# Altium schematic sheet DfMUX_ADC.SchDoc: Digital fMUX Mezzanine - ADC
size 513 x 386 mm; Engineer: M.Dobbs, McGill U.; Revision: 4
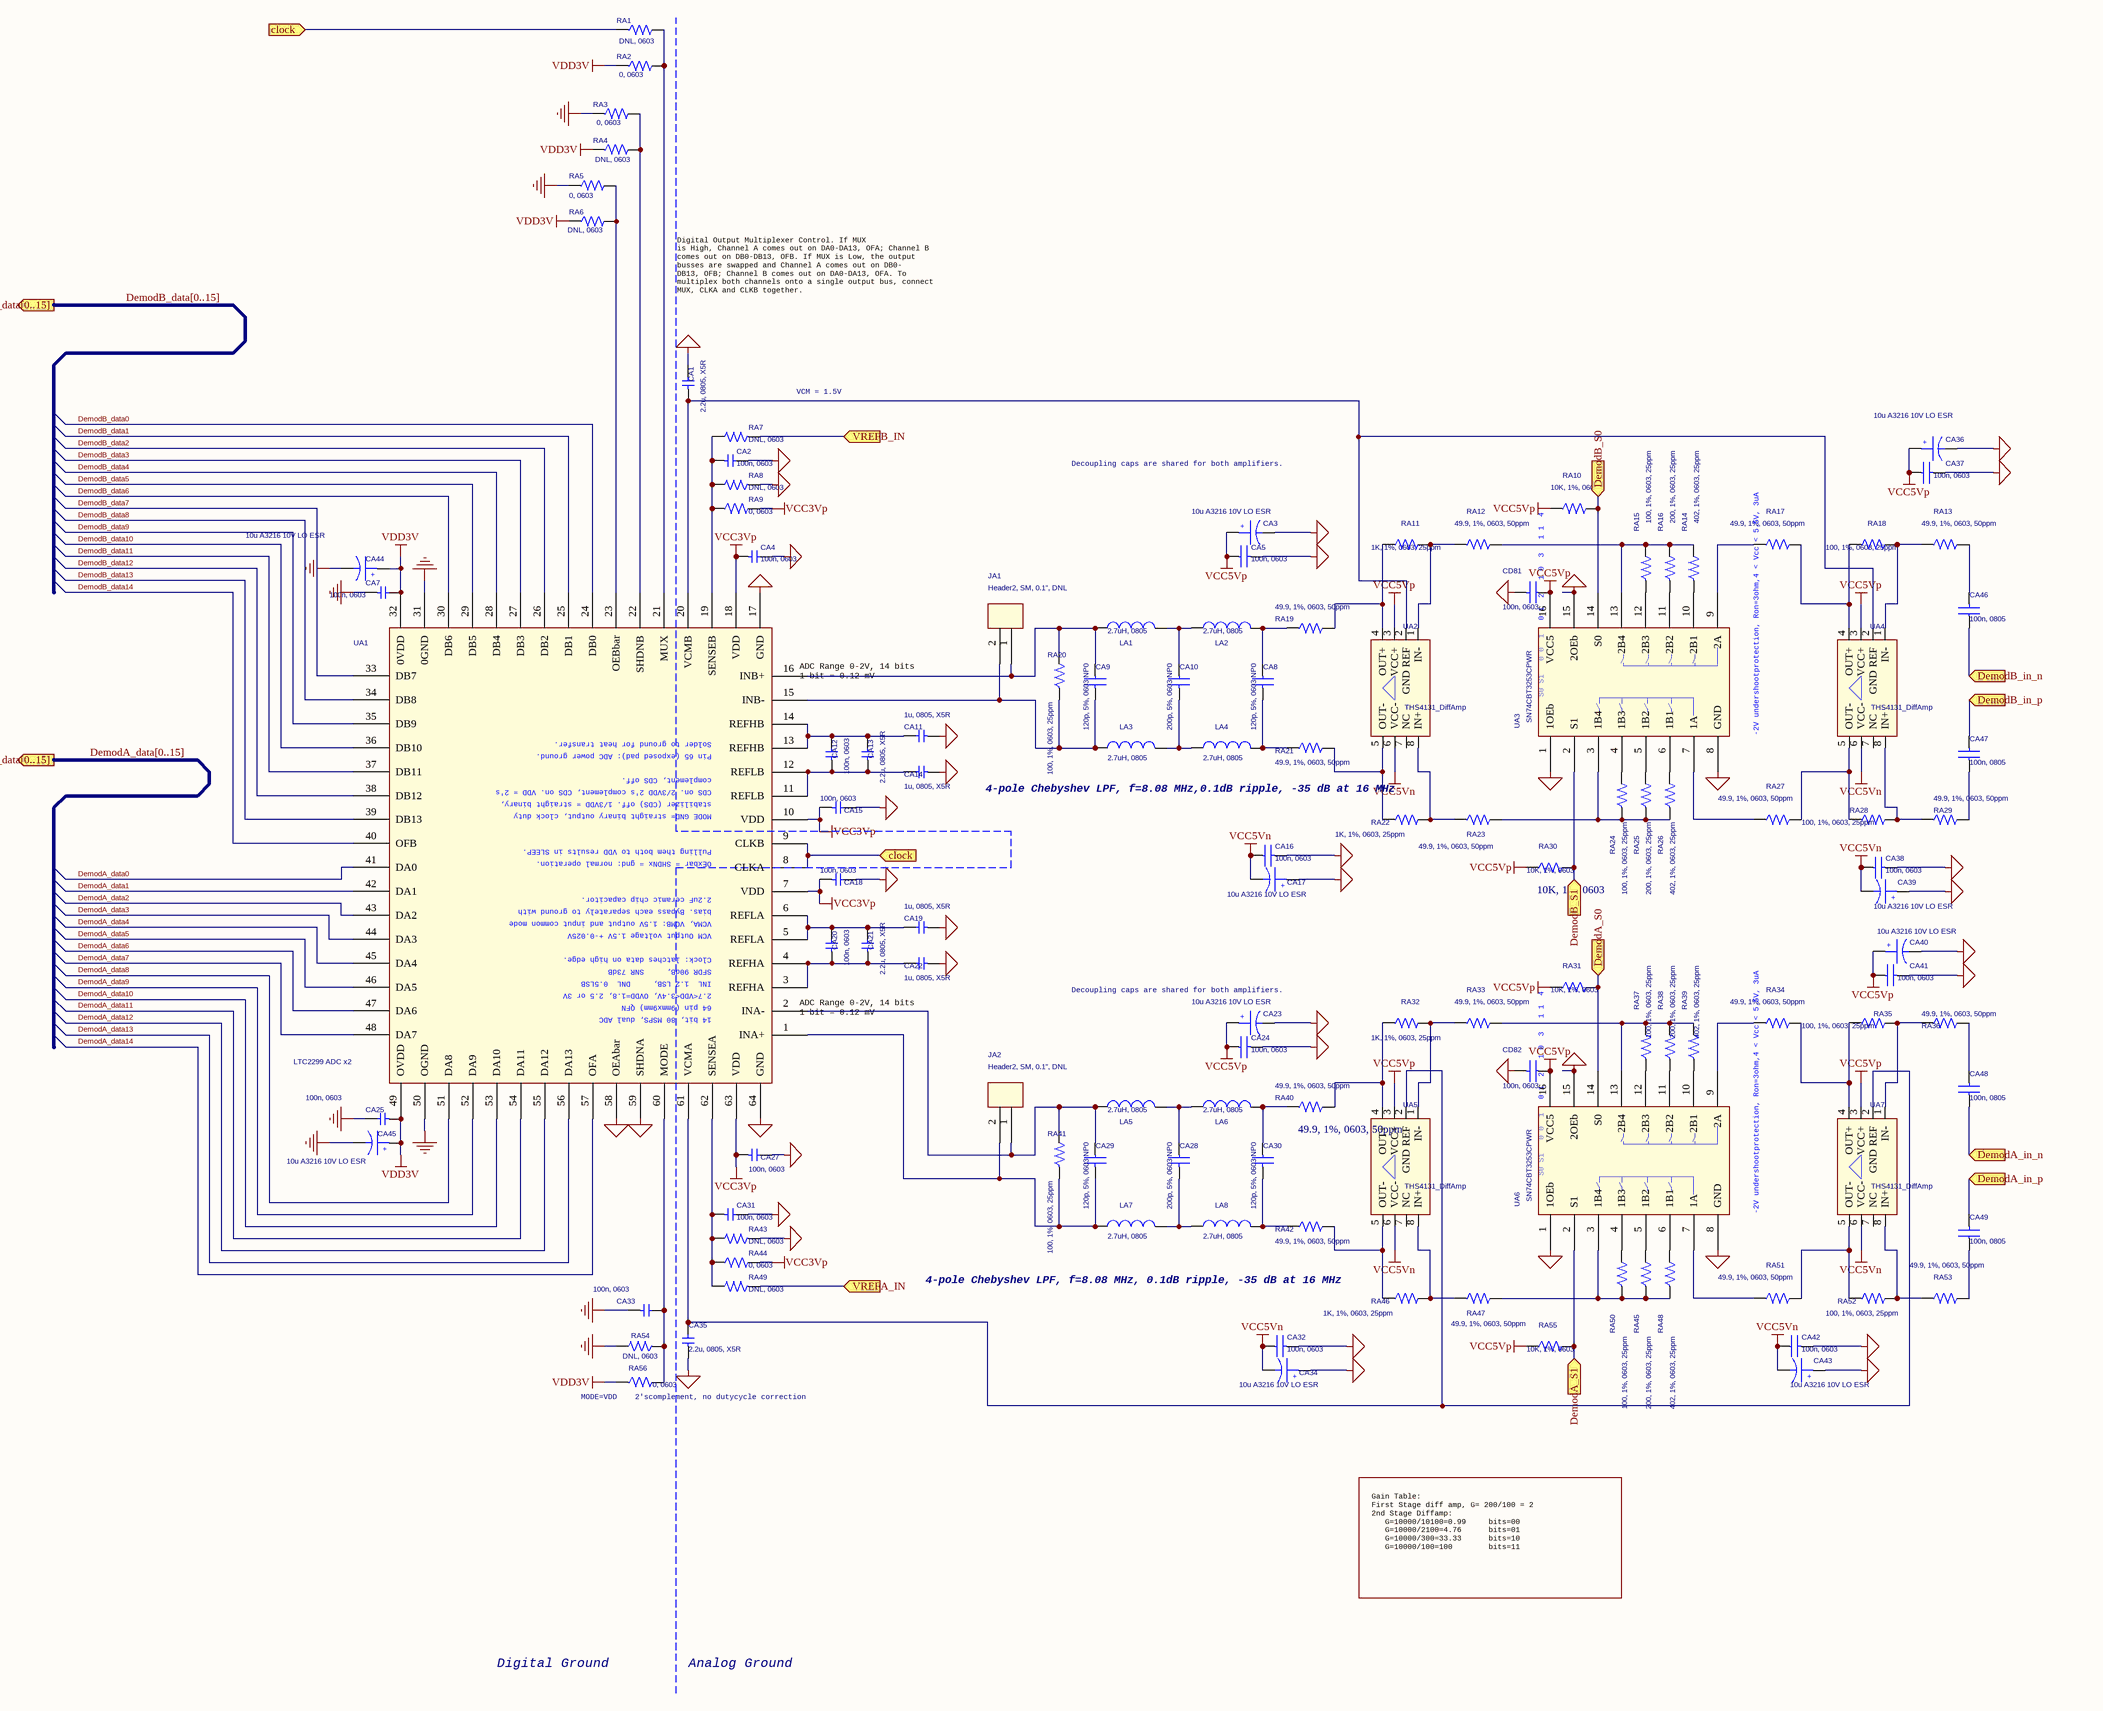
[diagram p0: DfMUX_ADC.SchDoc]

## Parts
CA1  2.2u, 0805, X5R  [CK05]
CA2  100n, 0603  [CK05]
CA3  10u A3216 10V LO ESR  [TANTA]
CA4  100n, 0603  [CK05]
CA5  100n, 0603  [0603c]
CA7  100n, 0603  [CK05]
CA8  120p, 5%, 0603 NP0  [0603c]
CA9  120p, 5%, 0603 NP0  [0603c]
CA10  200p, 5%, 0603 NP0  [0603c]
CA11  1u, 0805, X5R  [CK05]
CA12  100n, 0603  [CK05]
CA13  2.2u, 0805, X5R  [CK05]
CA14  1u, 0805, X5R  [CK05]
CA15  100n, 0603  [CK05]
CA16  100n, 0603  [0603c]
CA17  10u A3216 10V LO ESR  [TANTA]
CA18  100n, 0603  [CK05]
CA19  1u, 0805, X5R  [CK05]
CA20  100n, 0603  [CK05]
CA21  2.2u, 0805, X5R  [CK05]
CA22  1u, 0805, X5R  [CK05]
CA23  10u A3216 10V LO ESR  [TANTA]
CA24  100n, 0603  [0603c]
CA25  100n, 0603  [CK05]
CA27  100n, 0603  [CK05]
CA28  200p, 5%, 0603 NP0  [0603C_REV1]
CA29  120p, 5%, 0603 NP0  [0603c]
CA30  120p, 5%, 0603 NP0  [0603c]
CA31  100n, 0603  [CK05]
CA32  100n, 0603  [0603c]
CA33  100n, 0603  [CK05]
CA34  10u A3216 10V LO ESR  [TANTA]
CA35  2.2u, 0805, X5R  [CK05]
CA36  10u A3216 10V LO ESR  [TANTA]
CA37  100n, 0603  [0603c]
CA38  100n, 0603  [0603c]
CA39  10u A3216 10V LO ESR  [TANTA]
CA40  10u A3216 10V LO ESR  [TANTA]
CA41  100n, 0603  [0603c]
CA42  100n, 0603  [0603c]
CA43  10u A3216 10V LO ESR  [TANTA]
CA44  10u A3216 10V LO ESR  [TANTA]
CA45  10u A3216 10V LO ESR  [TANTA]
CA46  100n, 0805  [0805c]
CA47  100n, 0805  [0805c]
CA48  100n, 0805  [0805c]
CA49  100n, 0805  [0805c]
CD81  100n, 0603  [0603c]
CD82  100n, 0603  [0603c]
JA1  Header2, SM, 0.1", DNL  [HEADER_AMP146128]
JA2  Header2, SM, 0.1", DNL  [HEADER_AMP146128]
LA1  2.7uH, 0805  [0805L]
LA2  2.7uH, 0805  [0805L]
LA3  2.7uH, 0805  [0805L]
LA4  2.7uH, 0805  [0805L]
LA5  2.7uH, 0805  [0805L]
LA6  2.7uH, 0805  [0805L]
LA7  2.7uH, 0805  [0805L]
LA8  2.7uH, 0805  [0805L]
RA1  DNL, 0603  [RC05]
RA2  0, 0603  [RC05]
RA3  0, 0603  [RC05]
RA4  DNL, 0603  [RC05]
RA5  0, 0603  [RC05]
RA6  DNL, 0603  [RC05]
RA7  DNL, 0603  [RC05]
RA8  DNL, 0603  [RC05]
RA9  0, 0603  [RC05]
RA10  10K, 1%, 0603  [RC05]
RA11  1K, 1%, 0603, 25ppm  [RC05]
RA12  49.9, 1%, 0603, 50ppm  [RC05]
RA13  49.9, 1%, 0603, 50ppm  [RC05]
RA14  402, 1%, 0603, 25ppm  [RC05]
RA15  100, 1%, 0603, 25ppm  [RC05]
RA16  200, 1%, 0603, 25ppm  [RC05]
RA17  49.9, 1%, 0603, 50ppm  [RC05]
RA18  100, 1%, 0603, 25ppm  [RC05]
RA19  49.9, 1%, 0603, 50ppm  [RC05]
RA20  100, 1%, 0603, 25ppm  [RC05]
RA21  49.9, 1%, 0603, 50ppm  [RC05]
RA22  1K, 1%, 0603, 25ppm  [RC05]
RA23  49.9, 1%, 0603, 50ppm  [RC05]
RA24  100, 1%, 0603, 25ppm  [RC05]
RA25  200, 1%, 0603, 25ppm  [RC05]
RA26  402, 1%, 0603, 25ppm  [RC05]
RA27  49.9, 1%, 0603, 50ppm  [RC05]
RA28  100, 1%, 0603, 25ppm  [RC05]
RA29  49.9, 1%, 0603, 50ppm  [RC05]
RA30  10K, 1%, 0603  [RC05]
RA31  10K, 1%, 0603  [RC05]
RA32  1K, 1%, 0603, 25ppm  [RC05]
RA33  49.9, 1%, 0603, 50ppm  [RC05]
RA34  49.9, 1%, 0603, 50ppm  [RC05]
RA35  100, 1%, 0603, 25ppm  [RC05]
RA36  49.9, 1%, 0603, 50ppm  [RC05]
RA37  100, 1%, 0603, 25ppm  [RC05]
RA38  200, 1%, 0603, 25ppm  [RC05]
RA39  402, 1%, 0603, 25ppm  [RC05]
RA40  49.9, 1%, 0603, 50ppm  [RC05]
RA41  100, 1%, 0603, 25ppm  [RC05]
RA42  49.9, 1%, 0603, 50ppm  [RC05]
RA43  DNL, 0603  [RC05]
RA44  0, 0603  [RC05]
RA45  200, 1%, 0603, 25ppm  [RC05]
RA46  1K, 1%, 0603, 25ppm  [RC05]
RA47  49.9, 1%, 0603, 50ppm  [RC05]
RA48  402, 1%, 0603, 25ppm  [RC05]
RA49  DNL, 0603  [RC05]
RA50  100, 1%, 0603, 25ppm  [RC05]
RA51  49.9, 1%, 0603, 50ppm  [RC05]
RA52  100, 1%, 0603, 25ppm  [RC05]
RA53  49.9, 1%, 0603, 50ppm  [RC05]
RA54  DNL, 0603  [RC05]
RA55  10K, 1%, 0603  [RC05]
RA56  0, 0603  [RC05]
UA1  LTC2299 ADC x2  [QFN64]
UA2  THS4131_DiffAmp  [SOIC8]
UA3  SN74CBT3253CPWR  [TSSOP16]
UA4  THS4131_DiffAmp  [SOIC8]
UA5  THS4131_DiffAmp  [SOIC8]
UA6  SN74CBT3253CPWR  [TSSOP16]
UA7  THS4131_DiffAmp  [SOIC8]

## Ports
clock, DemodA_data[0..15], DemodA_in_n, DemodA_in_p, DemodA_S0, DemodA_S1, DemodB_data[0..15], DemodB_in_n, DemodB_in_p, DemodB_S0, DemodB_S1, VREFA_IN, VREFB_IN

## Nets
GND_DIG: CA7.1 CA25.2 CA33.1 CA44.2 CA45.2 RA3.1 RA5.1 RA54.2 UA1.31(0GND) UA1.50(OGND)
GND_SIGNAL: CA1.2 CA2.2 CA3.2 CA4.2 CA5.2 CA11.1 CA14.1 CA15.2 CA16.2 CA17.1 CA18.2 CA19.1 CA22.1 CA23.2 CA24.2 CA27.2 CA31.2 CA32.2 CA34.1 CA35.1 CA36.2 CA37.2 CA38.2 CA39.1 CA40.2 CA41.2 CA42.2 CA43.1 CD81.2 CD82.2 RA8.1 RA43.1 UA1.17(GND) UA1.58(OEAbar) UA1.59(SHDNA) UA1.64(GND) UA3.1(1OEb) UA3.8(GND) UA3.15(2OEb) UA6.1(1OEb) UA6.8(GND) UA6.15(2OEb)
VCC3Vp: CA4.1 CA15.1 CA18.1 CA27.1 RA9.2 RA44.2 UA1.7(VDD) UA1.10(VDD) UA1.18(VDD) UA1.63(VDD)
VCC5Vn: CA16.1 CA17.2 CA32.1 CA34.2 CA38.1 CA39.2 CA42.1 CA43.2 UA2.6(VCC-) UA4.6(VCC-) UA5.6(VCC-) UA7.6(VCC-)
VCC5Vp: CA3.1 CA5.1 CA23.1 CA24.1 CA36.1 CA37.1 CA40.1 CA41.1 CD81.1 CD82.1 RA10.1 RA30.1 RA31.1 RA55.1 UA2.3(VCC+) UA3.16(VCC5) UA4.3(VCC+) UA5.3(VCC+) UA6.16(VCC5) UA7.3(VCC+)
VDD3V: CA7.2 CA25.1 CA44.1 CA45.1 RA2.1 RA4.1 RA6.1 RA56.1 UA1.32(0VDD) UA1.49(OVDD)
clock: RA1.1 UA1.8(CLKA) UA1.9(CLKB) ; port clock
DemodA_data0: UA1.41(DA0)
DemodA_data1: UA1.42(DA1)
DemodA_data2: UA1.43(DA2)
DemodA_data3: UA1.44(DA3)
DemodA_data4: UA1.45(DA4)
DemodA_data5: UA1.46(DA5)
DemodA_data6: UA1.47(DA6)
DemodA_data7: UA1.48(DA7)
DemodA_data8: UA1.51(DA8)
DemodA_data9: UA1.52(DA9)
DemodA_data10: UA1.53(DA10)
DemodA_data11: UA1.54(DA11)
DemodA_data12: UA1.55(DA12)
DemodA_data13: UA1.56(DA13)
DemodA_data14: UA1.57(OFA)
DemodA_in_n: CA48.1 ; port DemodA_in_n
DemodA_in_p: CA49.2 ; port DemodA_in_p
DemodA_S0: RA31.2 UA6.14(S0) ; port DemodA_S0
DemodA_S1: RA55.2 UA6.2(S1) ; port DemodA_S1
DemodB_data0: UA1.24(DB0)
DemodB_data1: UA1.25(DB1)
DemodB_data2: UA1.26(DB2)
DemodB_data3: UA1.27(DB3)
DemodB_data4: UA1.28(DB4)
DemodB_data5: UA1.29(DB5)
DemodB_data6: UA1.30(DB6)
DemodB_data7: UA1.33(DB7)
DemodB_data8: UA1.34(DB8)
DemodB_data9: UA1.35(DB9)
DemodB_data10: UA1.36(DB10)
DemodB_data11: UA1.37(DB11)
DemodB_data12: UA1.38(DB12)
DemodB_data13: UA1.39(DB13)
DemodB_data14: UA1.40(OFB)
DemodB_in_n: CA46.1 ; port DemodB_in_n
DemodB_in_p: CA47.2 ; port DemodB_in_p
DemodB_S0: RA10.2 UA3.14(S0) ; port DemodB_S0
DemodB_S1: RA30.2 UA3.2(S1) ; port DemodB_S1
VREFA_IN: RA49.1 ; port VREFA_IN
VREFB_IN: RA7.1 ; port VREFB_IN
NetCA1_1: CA1.1 UA1.20(VCMB) UA2.2(GND_REF) UA4.2(GND_REF)
NetCA2_1: CA2.1 RA7.2 RA8.2 RA9.1 UA1.19(SENSEB)
NetCA8_1: CA8.1 LA2.2 RA19.1
NetCA8_2: CA8.2 LA4.2 RA21.1
NetCA9_1: CA9.1 JA1.1 LA1.1 RA20.2 UA1.16(INB+)
NetCA9_2: CA9.2 JA1.2 LA3.1 RA20.1 UA1.15(INB-)
NetCA10_1: CA10.1 LA1.2 LA2.1
NetCA10_2: CA10.2 LA3.2 LA4.1
NetCA11_2: CA11.2 CA12.2 CA13.2 UA1.13(REFHB) UA1.14(REFHB)
NetCA12_1: CA12.1 CA13.1 CA14.2 UA1.11(REFLB) UA1.12(REFLB)
NetCA19_2: CA19.2 CA20.2 CA21.2 UA1.5(REFLA) UA1.6(REFLA)
NetCA20_1: CA20.1 CA21.1 CA22.2 UA1.3(REFHA) UA1.4(REFHA)
NetCA28_1: CA28.1 LA5.2 LA6.1
NetCA28_2: CA28.2 LA7.2 LA8.1
NetCA29_1: CA29.1 JA2.1 LA5.1 RA41.2 UA1.2(INA-)
NetCA29_2: CA29.2 JA2.2 LA7.1 RA41.1 UA1.1(INA+)
NetCA30_1: CA30.1 LA6.2 RA40.1
NetCA30_2: CA30.2 LA8.2 RA42.1
NetCA31_1: CA31.1 RA43.2 RA44.1 RA49.2 UA1.62(SENSEA)
NetCA33_2: CA33.2 RA54.1 RA56.2 UA1.60(MODE)
NetCA35_2: CA35.2 UA1.61(VCMA) UA5.2(GND_REF) UA7.2(GND_REF)
NetCA46_2: CA46.2 RA13.2
NetCA47_1: CA47.1 RA29.2
NetCA48_2: CA48.2 RA36.2
NetCA49_1: CA49.1 RA53.2
NetRA1_2: RA1.2 RA2.2 UA1.21(MUX)
NetRA3_2: RA3.2 RA4.2 UA1.22(SHDNB)
NetRA5_2: RA5.2 RA6.2 UA1.23(OEBbar)
NetRA11_1: RA11.1 RA19.2 UA2.4(OUT+)
NetRA11_2: RA11.2 RA12.1 UA2.1(IN-)
NetRA12_2: RA12.2 RA14.2 RA15.2 RA16.2 UA3.13(2B4)
NetRA13_1: RA13.1 RA18.2 UA4.1(IN-)
NetRA14_1: RA14.1 UA3.10(2B1)
NetRA15_1: RA15.1 UA3.12(2B3)
NetRA16_1: RA16.1 UA3.11(2B2)
NetRA17_1: RA17.1 UA3.9(2A)
NetRA17_2: RA17.2 RA18.1 UA4.4(OUT+)
NetRA21_2: RA21.2 RA22.1 UA2.5(OUT-)
NetRA22_2: RA22.2 RA23.1 UA2.8(IN+)
NetRA23_2: RA23.2 RA24.1 RA25.1 RA26.1 UA3.3(1B4)
NetRA24_2: RA24.2 UA3.4(1B3)
NetRA25_2: RA25.2 UA3.5(1B2)
NetRA26_2: RA26.2 UA3.6(1B1)
NetRA27_1: RA27.1 UA3.7(1A)
NetRA27_2: RA27.2 RA28.1 UA4.5(OUT-)
NetRA28_2: RA28.2 RA29.1 UA4.8(IN+)
NetRA32_1: RA32.1 RA40.2 UA5.4(OUT+)
NetRA32_2: RA32.2 RA33.1 UA5.1(IN-)
NetRA33_2: RA33.2 RA37.2 RA38.2 RA39.2 UA6.13(2B4)
NetRA34_1: RA34.1 UA6.9(2A)
NetRA34_2: RA34.2 RA35.1 UA7.4(OUT+)
NetRA35_2: RA35.2 RA36.1 UA7.1(IN-)
NetRA37_1: RA37.1 UA6.12(2B3)
NetRA38_1: RA38.1 UA6.11(2B2)
NetRA39_1: RA39.1 UA6.10(2B1)
NetRA42_2: RA42.2 RA46.1 UA5.5(OUT-)
NetRA45_1: RA45.1 RA47.2 RA48.1 RA50.1 UA6.3(1B4)
NetRA45_2: RA45.2 UA6.5(1B2)
NetRA46_2: RA46.2 RA47.1 UA5.8(IN+)
NetRA48_2: RA48.2 UA6.6(1B1)
NetRA50_2: RA50.2 UA6.4(1B3)
NetRA51_1: RA51.1 UA6.7(1A)
NetRA51_2: RA51.2 RA52.1 UA7.5(OUT-)
NetRA52_2: RA52.2 RA53.1 UA7.8(IN+)

Not connected (* = marked no-connect by the designer): UA2 7(NC); UA4 7(NC); UA5 7(NC); UA7 7(NC)

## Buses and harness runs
bus DemodA_data[0..15] = port DemodA_data[0..15]
bus DemodB_data[0..15] = port DemodB_data[0..15]

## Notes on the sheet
- (near CA1) Digital Output Multiplexer Control. If MUX
  is High, Channel A comes out on DA0-DA13, OFA; Channel B
  comes out on DB0-DB13, OFB. If MUX is Low, the output
  busses are swapped and Channel A comes out on DB0-
  DB13, OFB; Channel B comes out on DA0-DA13, OFA. To
  multiplex both channels onto a single output bus, connect
  MUX, CLKA and CLKB together.
- VCM = 1.5V
- Decoupling caps are shared for both amplifiers.
- ADC Range 0-2V, 14 bits
  1 bit = 0.12 mV
- 4-pole Chebyshev LPF, f=8.08 MHz,0.1dB ripple, -35 dB at 16 MHz
- (near CA23) Decoupling caps are shared for both amplifiers.
- 4-pole Chebyshev LPF, f=8.08 MHz, 0.1dB ripple, -35 dB at 16 MHz
- (near RA56) MODE=VDD    2'scomplement, no dutycycle correction
- Gain Table:
  First Stage diff amp, G= 200/100 = 2
  2nd Stage Diffamp:
  G=10000/10100=0.99     bits=00
  G=10000/2100=4.76      bits=01
  G=10000/300=33.33      bits=10
  G=10000/100=100        bits=11
- Digital Ground
- Analog Ground

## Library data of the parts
CA1 = C: PSpiceTemplate: C^@REFDES %1 %2 ?TOLERANCE|C^@REFDES| @VALUE ?IC/IC=@IC/ ?TOLERANCE|\n.model C^@REFDES CAP C=1 DEV=@TOLERANCE%|; COMPGROUP: 1; COMPFIXED: NO; COMPHEIGHT: 0.000; COMPLOC: [2632.633,2251.433]; COMPROT: 180; COMPSIDE: TOP
CA2 = C: PSpiceTemplate: C^@REFDES %1 %2 ?TOLERANCE|C^@REFDES| @VALUE ?IC/IC=@IC/ ?TOLERANCE|\n.model C^@REFDES CAP C=1 DEV=@TOLERANCE%|; COMPGROUP: 1; COMPFIXED: NO; COMPHEIGHT: 0.000; COMPLOC: [2197.633,2146.433]; COMPROT: 270; COMPSIDE: TOP
CA3 = CAPACITOR POL: COMPGROUP: 1; COMPFIXED: NO; COMPHEIGHT: 0.000; COMPLOC: [2892.633,2246.433]; COMPROT: 0; COMPSIDE: TOP
CA4 = C: PSpiceTemplate: C^@REFDES %1 %2 ?TOLERANCE|C^@REFDES| @VALUE ?IC/IC=@IC/ ?TOLERANCE|\n.model C^@REFDES CAP C=1 DEV=@TOLERANCE%|; COMPGROUP: 1; COMPFIXED: NO; COMPHEIGHT: 0.000; COMPLOC: [2117.633,2006.433]; COMPROT: 0; COMPSIDE: BOT
CA5 = CAPACITOR NON-POL: COMPGROUP: 1; COMPFIXED: NO; COMPHEIGHT: 0.000; COMPLOC: [2784.633,2230.000]; COMPROT: 180; COMPSIDE: TOP
CA7 = C: PSpiceTemplate: C^@REFDES %1 %2 ?TOLERANCE|C^@REFDES| @VALUE ?IC/IC=@IC/ ?TOLERANCE|\n.model C^@REFDES CAP C=1 DEV=@TOLERANCE%|; COMPGROUP: 1; COMPFIXED: NO; COMPHEIGHT: 0.000; COMPLOC: [1800.633,2003.433]; COMPROT: 270; COMPSIDE: BOT
CA8 = CAPACITOR NON-POL: COMPGROUP: 1; COMPFIXED: NO; COMPHEIGHT: 0.000; COMPLOC: [2737.633,1986.433]; COMPROT: 270; COMPSIDE: TOP
CA9 = CAPACITOR NON-POL: COMPGROUP: 1; COMPFIXED: NO; COMPHEIGHT: 0.000; COMPLOC: [2542.633,2136.433]; COMPROT: 270; COMPSIDE: TOP
CA10 = CAPACITOR NON-POL: COMPGROUP: 1; COMPFIXED: NO; COMPHEIGHT: 0.000; COMPLOC: [2607.633,2006.433]; COMPROT: 270; COMPSIDE: TOP
CA11 = C: PSpiceTemplate: C^@REFDES %1 %2 ?TOLERANCE|C^@REFDES| @VALUE ?IC/IC=@IC/ ?TOLERANCE|\n.model C^@REFDES CAP C=1 DEV=@TOLERANCE%|; COMPGROUP: 1; COMPFIXED: NO; COMPHEIGHT: 0.000; COMPLOC: [2417.633,2011.433]; COMPROT: 180; COMPSIDE: TOP
CA12 = C: PSpiceTemplate: C^@REFDES %1 %2 ?TOLERANCE|C^@REFDES| @VALUE ?IC/IC=@IC/ ?TOLERANCE|\n.model C^@REFDES CAP C=1 DEV=@TOLERANCE%|; COMPGROUP: 1; COMPFIXED: NO; COMPHEIGHT: 0.000; COMPLOC: [2202.633,1946.433]; COMPROT: 90; COMPSIDE: TOP
CA13 = C: PSpiceTemplate: C^@REFDES %1 %2 ?TOLERANCE|C^@REFDES| @VALUE ?IC/IC=@IC/ ?TOLERANCE|\n.model C^@REFDES CAP C=1 DEV=@TOLERANCE%|; COMPGROUP: 1; COMPFIXED: NO; COMPHEIGHT: 0.000; COMPLOC: [2269.633,1929.433]; COMPROT: 90; COMPSIDE: TOP
CA14 = C: PSpiceTemplate: C^@REFDES %1 %2 ?TOLERANCE|C^@REFDES| @VALUE ?IC/IC=@IC/ ?TOLERANCE|\n.model C^@REFDES CAP C=1 DEV=@TOLERANCE%|; COMPGROUP: 1; COMPFIXED: NO; COMPHEIGHT: 0.000; COMPLOC: [2417.633,1931.433]; COMPROT: 180; COMPSIDE: TOP
CA15 = C: PSpiceTemplate: C^@REFDES %1 %2 ?TOLERANCE|C^@REFDES| @VALUE ?IC/IC=@IC/ ?TOLERANCE|\n.model C^@REFDES CAP C=1 DEV=@TOLERANCE%|; COMPGROUP: 1; COMPFIXED: NO; COMPHEIGHT: 0.000; COMPLOC: [2072.633,1951.433]; COMPROT: 0; COMPSIDE: BOT
CA16 = CAPACITOR NON-POL: COMPGROUP: 1; COMPFIXED: NO; COMPHEIGHT: 0.000; COMPLOC: [2877.633,2006.433]; COMPROT: 180; COMPSIDE: BOT
CA17 = CAPACITOR POL: COMPGROUP: 1; COMPFIXED: NO; COMPHEIGHT: 0.000; COMPLOC: [2712.633,2081.433]; COMPROT: 180; COMPSIDE: BOT
CA18 = C: PSpiceTemplate: C^@REFDES %1 %2 ?TOLERANCE|C^@REFDES| @VALUE ?IC/IC=@IC/ ?TOLERANCE|\n.model C^@REFDES CAP C=1 DEV=@TOLERANCE%|; COMPGROUP: 1; COMPFIXED: NO; COMPHEIGHT: 0.000; COMPLOC: [2072.633,1866.433]; COMPROT: 0; COMPSIDE: BOT
CA19 = C: PSpiceTemplate: C^@REFDES %1 %2 ?TOLERANCE|C^@REFDES| @VALUE ?IC/IC=@IC/ ?TOLERANCE|\n.model C^@REFDES CAP C=1 DEV=@TOLERANCE%|; COMPGROUP: 1; COMPFIXED: NO; COMPHEIGHT: 0.000; COMPLOC: [2414.633,1853.433]; COMPROT: 180; COMPSIDE: TOP
CA20 = C: PSpiceTemplate: C^@REFDES %1 %2 ?TOLERANCE|C^@REFDES| @VALUE ?IC/IC=@IC/ ?TOLERANCE|\n.model C^@REFDES CAP C=1 DEV=@TOLERANCE%|; COMPGROUP: 1; COMPFIXED: NO; COMPHEIGHT: 0.000; COMPLOC: [2202.633,1796.433]; COMPROT: 90; COMPSIDE: TOP
CA21 = C: PSpiceTemplate: C^@REFDES %1 %2 ?TOLERANCE|C^@REFDES| @VALUE ?IC/IC=@IC/ ?TOLERANCE|\n.model C^@REFDES CAP C=1 DEV=@TOLERANCE%|; COMPGROUP: 1; COMPFIXED: NO; COMPHEIGHT: 0.000; COMPLOC: [2267.633,1771.433]; COMPROT: 90; COMPSIDE: TOP
CA22 = C: PSpiceTemplate: C^@REFDES %1 %2 ?TOLERANCE|C^@REFDES| @VALUE ?IC/IC=@IC/ ?TOLERANCE|\n.model C^@REFDES CAP C=1 DEV=@TOLERANCE%|; COMPGROUP: 1; COMPFIXED: NO; COMPHEIGHT: 0.000; COMPLOC: [2416.633,1771.433]; COMPROT: 180; COMPSIDE: TOP
CA23 = CAPACITOR POL: COMPGROUP: 1; COMPFIXED: NO; COMPHEIGHT: 0.000; COMPLOC: [2892.633,1751.433]; COMPROT: 0; COMPSIDE: TOP
CA24 = CAPACITOR NON-POL: COMPGROUP: 1; COMPFIXED: NO; COMPHEIGHT: 0.000; COMPLOC: [2792.633,1731.433]; COMPROT: 180; COMPSIDE: TOP
CA25 = C: PSpiceTemplate: C^@REFDES %1 %2 ?TOLERANCE|C^@REFDES| @VALUE ?IC/IC=@IC/ ?TOLERANCE|\n.model C^@REFDES CAP C=1 DEV=@TOLERANCE%|; COMPGROUP: 1; COMPFIXED: NO; COMPHEIGHT: 0.000; COMPLOC: [1802.633,1761.433]; COMPROT: 270; COMPSIDE: BOT
CA27 = C: PSpiceTemplate: C^@REFDES %1 %2 ?TOLERANCE|C^@REFDES| @VALUE ?IC/IC=@IC/ ?TOLERANCE|\n.model C^@REFDES CAP C=1 DEV=@TOLERANCE%|; COMPGROUP: 1; COMPFIXED: NO; COMPHEIGHT: 0.000; COMPLOC: [2168.633,1683.367]; COMPROT: 0; COMPSIDE: TOP
CA28 = CAPACITOR NON-POL: COMPGROUP: 1; COMPFIXED: NO; COMPHEIGHT: 0.000; COMPLOC: [2607.633,1521.433]; COMPROT: 270; COMPSIDE: TOP; FPLIST: 0805L
CA29 = CAPACITOR NON-POL: COMPGROUP: 1; COMPFIXED: NO; COMPHEIGHT: 0.000; COMPLOC: [2592.633,1641.433]; COMPROT: 270; COMPSIDE: TOP
CA30 = CAPACITOR NON-POL: COMPGROUP: 1; COMPFIXED: NO; COMPHEIGHT: 0.000; COMPLOC: [2737.633,1491.433]; COMPROT: 270; COMPSIDE: TOP
CA31 = C: PSpiceTemplate: C^@REFDES %1 %2 ?TOLERANCE|C^@REFDES| @VALUE ?IC/IC=@IC/ ?TOLERANCE|\n.model C^@REFDES CAP C=1 DEV=@TOLERANCE%|; COMPGROUP: 1; COMPFIXED: NO; COMPHEIGHT: 0.000; COMPLOC: [2070.000,1815.000]; COMPROT: 0; COMPSIDE: BOT
CA32 = CAPACITOR NON-POL: COMPGROUP: 1; COMPFIXED: NO; COMPHEIGHT: 0.000; COMPLOC: [2877.633,1511.433]; COMPROT: 180; COMPSIDE: BOT
CA33 = C: PSpiceTemplate: C^@REFDES %1 %2 ?TOLERANCE|C^@REFDES| @VALUE ?IC/IC=@IC/ ?TOLERANCE|\n.model C^@REFDES CAP C=1 DEV=@TOLERANCE%|; COMPGROUP: 1; COMPFIXED: NO; COMPHEIGHT: 0.000; COMPLOC: [2012.633,1624.367]; COMPROT: 90; COMPSIDE: TOP
CA34 = CAPACITOR POL: COMPGROUP: 1; COMPFIXED: NO; COMPHEIGHT: 0.000; COMPLOC: [2712.633,1586.433]; COMPROT: 180; COMPSIDE: BOT
CA35 = C: PSpiceTemplate: C^@REFDES %1 %2 ?TOLERANCE|C^@REFDES| @VALUE ?IC/IC=@IC/ ?TOLERANCE|\n.model C^@REFDES CAP C=1 DEV=@TOLERANCE%|; COMPGROUP: 1; COMPFIXED: NO; COMPHEIGHT: 0.000; COMPLOC: [2547.633,1756.433]; COMPROT: 0; COMPSIDE: TOP
CA36 = CAPACITOR POL: COMPGROUP: 1; COMPFIXED: NO; COMPHEIGHT: 0.000; COMPLOC: [3567.633,2246.433]; COMPROT: 180; COMPSIDE: TOP
CA37 = CAPACITOR NON-POL: COMPGROUP: 1; COMPFIXED: NO; COMPHEIGHT: 0.000; COMPLOC: [3622.633,2246.433]; COMPROT: 0; COMPSIDE: TOP
CA38 = CAPACITOR NON-POL: COMPGROUP: 1; COMPFIXED: NO; COMPHEIGHT: 0.000; COMPLOC: [3606.633,2036.433]; COMPROT: 180; COMPSIDE: BOT
CA39 = CAPACITOR POL: COMPGROUP: 1; COMPFIXED: NO; COMPHEIGHT: 0.000; COMPLOC: [3697.633,1966.433]; COMPROT: 0; COMPSIDE: BOT
CA40 = CAPACITOR POL: COMPGROUP: 1; COMPFIXED: NO; COMPHEIGHT: 0.000; COMPLOC: [3567.633,1751.433]; COMPROT: 180; COMPSIDE: TOP
CA41 = CAPACITOR NON-POL: COMPGROUP: 1; COMPFIXED: NO; COMPHEIGHT: 0.000; COMPLOC: [3622.633,1751.433]; COMPROT: 0; COMPSIDE: TOP
CA42 = CAPACITOR NON-POL: COMPGROUP: 1; COMPFIXED: NO; COMPHEIGHT: 0.000; COMPLOC: [3606.633,1531.433]; COMPROT: 180; COMPSIDE: BOT
CA43 = CAPACITOR POL: COMPGROUP: 1; COMPFIXED: NO; COMPHEIGHT: 0.000; COMPLOC: [3697.633,1461.433]; COMPROT: 0; COMPSIDE: BOT
CA44 = CAPACITOR POL: COMPGROUP: 1; COMPFIXED: NO; COMPHEIGHT: 0.000; COMPLOC: [1732.633,2131.433]; COMPROT: 90; COMPSIDE: BOT
CA45 = CAPACITOR POL: COMPGROUP: 1; COMPFIXED: NO; COMPHEIGHT: 0.000; COMPLOC: [1732.633,1686.433]; COMPROT: 270; COMPSIDE: BOT
CA46 = CAPACITOR NON-POL: COMPGROUP: 1; COMPFIXED: NO; COMPHEIGHT: 0.000; COMPLOC: [3869.633,2180.000]; COMPROT: 180; COMPSIDE: TOP
CA47 = CAPACITOR NON-POL: COMPGROUP: 1; COMPFIXED: NO; COMPHEIGHT: 0.000; COMPLOC: [3784.633,2105.000]; COMPROT: 0; COMPSIDE: TOP
CA48 = CAPACITOR NON-POL: COMPGROUP: 1; COMPFIXED: NO; COMPHEIGHT: 0.000; COMPLOC: [3874.633,1680.000]; COMPROT: 180; COMPSIDE: TOP
CA49 = CAPACITOR NON-POL: COMPGROUP: 1; COMPFIXED: NO; COMPHEIGHT: 0.000; COMPLOC: [3789.633,1605.000]; COMPROT: 0; COMPSIDE: TOP
CD81 = CAPACITOR NON-POL: COMPGROUP: 1; COMPFIXED: NO; COMPHEIGHT: 0.000; COMPLOC: [3172.633,2246.433]; COMPROT: 180; COMPSIDE: TOP
CD82 = CAPACITOR NON-POL: COMPGROUP: 1; COMPFIXED: NO; COMPHEIGHT: 0.000; COMPLOC: [3172.633,1746.433]; COMPROT: 180; COMPSIDE: TOP
JA1 = CONN_TRBLK_2: COMPGROUP: 1; COMPFIXED: NO; COMPHEIGHT: 0.000; COMPLOC: [2507.633,2186.433]; COMPROT: 270; COMPSIDE: TOP
JA2 = CONN_TRBLK_2: COMPGROUP: 1; COMPFIXED: NO; COMPHEIGHT: 0.000; COMPLOC: [2507.633,1691.433]; COMPROT: 270; COMPSIDE: TOP
LA1 = INDUCTOR/SM: COMPGROUP: 1; COMPFIXED: NO; COMPHEIGHT: 0.000; COMPLOC: [2662.633,2176.433]; COMPROT: 270; COMPSIDE: TOP
LA2 = INDUCTOR/SM: COMPGROUP: 1; COMPFIXED: NO; COMPHEIGHT: 0.000; COMPLOC: [2672.633,2031.433]; COMPROT: 270; COMPSIDE: TOP
LA3 = INDUCTOR/SM: COMPGROUP: 1; COMPFIXED: NO; COMPHEIGHT: 0.000; COMPLOC: [2542.633,2026.433]; COMPROT: 270; COMPSIDE: TOP
LA4 = INDUCTOR/SM: COMPGROUP: 1; COMPFIXED: NO; COMPHEIGHT: 0.000; COMPLOC: [2562.633,1881.433]; COMPROT: 0; COMPSIDE: TOP
LA5 = INDUCTOR/SM: COMPGROUP: 1; COMPFIXED: NO; COMPHEIGHT: 0.000; COMPLOC: [2662.633,1681.433]; COMPROT: 270; COMPSIDE: TOP
LA6 = INDUCTOR/SM: COMPGROUP: 1; COMPFIXED: NO; COMPHEIGHT: 0.000; COMPLOC: [2672.633,1536.433]; COMPROT: 270; COMPSIDE: TOP
LA7 = INDUCTOR/SM: COMPGROUP: 1; COMPFIXED: NO; COMPHEIGHT: 0.000; COMPLOC: [2539.633,1538.433]; COMPROT: 270; COMPSIDE: TOP
LA8 = INDUCTOR/SM: COMPGROUP: 1; COMPFIXED: NO; COMPHEIGHT: 0.000; COMPLOC: [2572.633,1391.433]; COMPROT: 0; COMPSIDE: TOP
RA1 = R_Dup2: PSpiceTemplate: R^@REFDES %1 %2 ?TOLERANCE|R^@REFDES| @VALUE  ?TOLERANCE|\n.model R^@REFDES RES R=1 DEV=@TOLERANCE%|; COMPGROUP: 1; COMPFIXED: NO; COMPHEIGHT: 0.000; COMPLOC: [1949.633,2050.000]; COMPROT: 180; COMPSIDE: BOT
RA2 = R_Dup2: PSpiceTemplate: R^@REFDES %1 %2 ?TOLERANCE|R^@REFDES| @VALUE  ?TOLERANCE|\n.model R^@REFDES RES R=1 DEV=@TOLERANCE%|; COMPGROUP: 1; COMPFIXED: NO; COMPHEIGHT: 0.000; COMPLOC: [2092.633,2151.433]; COMPROT: 180; COMPSIDE: TOP
RA3 = R_Dup2: PSpiceTemplate: R^@REFDES %1 %2 ?TOLERANCE|R^@REFDES| @VALUE  ?TOLERANCE|\n.model R^@REFDES RES R=1 DEV=@TOLERANCE%|; COMPGROUP: 1; COMPFIXED: NO; COMPHEIGHT: 0.000; COMPLOC: [2132.633,2206.433]; COMPROT: 180; COMPSIDE: TOP
RA4 = R_Dup2: PSpiceTemplate: R^@REFDES %1 %2 ?TOLERANCE|R^@REFDES| @VALUE  ?TOLERANCE|\n.model R^@REFDES RES R=1 DEV=@TOLERANCE%|; COMPGROUP: 1; COMPFIXED: NO; COMPHEIGHT: 0.000; COMPLOC: [2108.633,2261.433]; COMPROT: 180; COMPSIDE: TOP
RA5 = R_Dup2: PSpiceTemplate: R^@REFDES %1 %2 ?TOLERANCE|R^@REFDES| @VALUE  ?TOLERANCE|\n.model R^@REFDES RES R=1 DEV=@TOLERANCE%|; COMPGROUP: 1; COMPFIXED: NO; COMPHEIGHT: 0.000; COMPLOC: [1972.633,2206.433]; COMPROT: 0; COMPSIDE: TOP
RA6 = R_Dup2: PSpiceTemplate: R^@REFDES %1 %2 ?TOLERANCE|R^@REFDES| @VALUE  ?TOLERANCE|\n.model R^@REFDES RES R=1 DEV=@TOLERANCE%|; COMPGROUP: 1; COMPFIXED: NO; COMPHEIGHT: 0.000; COMPLOC: [1952.633,2261.433]; COMPROT: 0; COMPSIDE: TOP
RA7 = R_Dup2: PSpiceTemplate: R^@REFDES %1 %2 ?TOLERANCE|R^@REFDES| @VALUE  ?TOLERANCE|\n.model R^@REFDES RES R=1 DEV=@TOLERANCE%|; COMPGROUP: 1; COMPFIXED: NO; COMPHEIGHT: 0.000; COMPLOC: [2362.633,2204.367]; COMPROT: 180; COMPSIDE: TOP
RA8 = R_Dup2: PSpiceTemplate: R^@REFDES %1 %2 ?TOLERANCE|R^@REFDES| @VALUE  ?TOLERANCE|\n.model R^@REFDES RES R=1 DEV=@TOLERANCE%|; COMPGROUP: 1; COMPFIXED: NO; COMPHEIGHT: 0.000; COMPLOC: [2252.633,2091.433]; COMPROT: 90; COMPSIDE: TOP
RA9 = R_Dup2: PSpiceTemplate: R^@REFDES %1 %2 ?TOLERANCE|R^@REFDES| @VALUE  ?TOLERANCE|\n.model R^@REFDES RES R=1 DEV=@TOLERANCE%|; COMPGROUP: 1; COMPFIXED: NO; COMPHEIGHT: 0.000; COMPLOC: [2307.633,2151.433]; COMPROT: 0; COMPSIDE: TOP
RA10 = R_Dup2: PSpiceTemplate: R^@REFDES %1 %2 ?TOLERANCE|R^@REFDES| @VALUE  ?TOLERANCE|\n.model R^@REFDES RES R=1 DEV=@TOLERANCE%|; COMPGROUP: 1; COMPFIXED: NO; COMPHEIGHT: 0.000; COMPLOC: [3307.633,2246.433]; COMPROT: 180; COMPSIDE: TOP
RA11 = R_Dup2: PSpiceTemplate: R^@REFDES %1 %2 ?TOLERANCE|R^@REFDES| @VALUE  ?TOLERANCE|\n.model R^@REFDES RES R=1 DEV=@TOLERANCE%|; COMPGROUP: 1; COMPFIXED: NO; COMPHEIGHT: 0.000; COMPLOC: [3012.633,2036.433]; COMPROT: 90; COMPSIDE: TOP
RA12 = R_Dup2: PSpiceTemplate: R^@REFDES %1 %2 ?TOLERANCE|R^@REFDES| @VALUE  ?TOLERANCE|\n.model R^@REFDES RES R=1 DEV=@TOLERANCE%|; COMPGROUP: 1; COMPFIXED: NO; COMPHEIGHT: 0.000; COMPLOC: [3012.633,2135.433]; COMPROT: 90; COMPSIDE: TOP
RA13 = R_Dup2: PSpiceTemplate: R^@REFDES %1 %2 ?TOLERANCE|R^@REFDES| @VALUE  ?TOLERANCE|\n.model R^@REFDES RES R=1 DEV=@TOLERANCE%|; COMPGROUP: 1; COMPFIXED: NO; COMPHEIGHT: 0.000; COMPLOC: [3719.633,2134.000]; COMPROT: 90; COMPSIDE: TOP
RA14 = R_Dup2: PSpiceTemplate: R^@REFDES %1 %2 ?TOLERANCE|R^@REFDES| @VALUE  ?TOLERANCE|\n.model R^@REFDES RES R=1 DEV=@TOLERANCE%|; COMPGROUP: 1; COMPFIXED: NO; COMPHEIGHT: 0.000; COMPLOC: [3112.633,2081.433]; COMPROT: 180; COMPSIDE: TOP
RA15 = R_Dup2: PSpiceTemplate: R^@REFDES %1 %2 ?TOLERANCE|R^@REFDES| @VALUE  ?TOLERANCE|\n.model R^@REFDES RES R=1 DEV=@TOLERANCE%|; COMPGROUP: 1; COMPFIXED: NO; COMPHEIGHT: 0.000; COMPLOC: [3112.633,2191.433]; COMPROT: 180; COMPSIDE: TOP
RA16 = R_Dup2: PSpiceTemplate: R^@REFDES %1 %2 ?TOLERANCE|R^@REFDES| @VALUE  ?TOLERANCE|\n.model R^@REFDES RES R=1 DEV=@TOLERANCE%|; COMPGROUP: 1; COMPFIXED: NO; COMPHEIGHT: 0.000; COMPLOC: [3112.633,2136.433]; COMPROT: 180; COMPSIDE: TOP
RA17 = R_Dup2: PSpiceTemplate: R^@REFDES %1 %2 ?TOLERANCE|R^@REFDES| @VALUE  ?TOLERANCE|\n.model R^@REFDES RES R=1 DEV=@TOLERANCE%|; COMPGROUP: 1; COMPFIXED: NO; COMPHEIGHT: 0.000; COMPLOC: [3402.633,2181.433]; COMPROT: 0; COMPSIDE: TOP
RA18 = R_Dup2: PSpiceTemplate: R^@REFDES %1 %2 ?TOLERANCE|R^@REFDES| @VALUE  ?TOLERANCE|\n.model R^@REFDES RES R=1 DEV=@TOLERANCE%|; COMPGROUP: 1; COMPFIXED: NO; COMPHEIGHT: 0.000; COMPLOC: [3457.633,2136.433]; COMPROT: 270; COMPSIDE: TOP
RA19 = R_Dup2: PSpiceTemplate: R^@REFDES %1 %2 ?TOLERANCE|R^@REFDES| @VALUE  ?TOLERANCE|\n.model R^@REFDES RES R=1 DEV=@TOLERANCE%|; COMPGROUP: 1; COMPFIXED: NO; COMPHEIGHT: 0.000; COMPLOC: [2737.633,2031.433]; COMPROT: 90; COMPSIDE: TOP
RA20 = R_Dup2: PSpiceTemplate: R^@REFDES %1 %2 ?TOLERANCE|R^@REFDES| @VALUE  ?TOLERANCE|\n.model R^@REFDES RES R=1 DEV=@TOLERANCE%|; COMPGROUP: 1; COMPFIXED: NO; COMPHEIGHT: 0.000; COMPLOC: [2597.633,2081.433]; COMPROT: 90; COMPSIDE: TOP
RA21 = R_Dup2: PSpiceTemplate: R^@REFDES %1 %2 ?TOLERANCE|R^@REFDES| @VALUE  ?TOLERANCE|\n.model R^@REFDES RES R=1 DEV=@TOLERANCE%|; COMPGROUP: 1; COMPFIXED: NO; COMPHEIGHT: 0.000; COMPLOC: [2787.633,1876.433]; COMPROT: 0; COMPSIDE: TOP
RA22 = R_Dup2: PSpiceTemplate: R^@REFDES %1 %2 ?TOLERANCE|R^@REFDES| @VALUE  ?TOLERANCE|\n.model R^@REFDES RES R=1 DEV=@TOLERANCE%|; COMPGROUP: 1; COMPFIXED: NO; COMPHEIGHT: 0.000; COMPLOC: [2887.633,1876.433]; COMPROT: 0; COMPSIDE: TOP
RA23 = R_Dup2: PSpiceTemplate: R^@REFDES %1 %2 ?TOLERANCE|R^@REFDES| @VALUE  ?TOLERANCE|\n.model R^@REFDES RES R=1 DEV=@TOLERANCE%|; COMPGROUP: 1; COMPFIXED: NO; COMPHEIGHT: 0.000; COMPLOC: [3012.633,1971.433]; COMPROT: 270; COMPSIDE: TOP
RA24 = R_Dup2: PSpiceTemplate: R^@REFDES %1 %2 ?TOLERANCE|R^@REFDES| @VALUE  ?TOLERANCE|\n.model R^@REFDES RES R=1 DEV=@TOLERANCE%|; COMPGROUP: 1; COMPFIXED: NO; COMPHEIGHT: 0.000; COMPLOC: [3057.633,1916.433]; COMPROT: 0; COMPSIDE: TOP
RA25 = R_Dup2: PSpiceTemplate: R^@REFDES %1 %2 ?TOLERANCE|R^@REFDES| @VALUE  ?TOLERANCE|\n.model R^@REFDES RES R=1 DEV=@TOLERANCE%|; COMPGROUP: 1; COMPFIXED: NO; COMPHEIGHT: 0.000; COMPLOC: [3057.633,1971.433]; COMPROT: 0; COMPSIDE: TOP
RA26 = R_Dup2: PSpiceTemplate: R^@REFDES %1 %2 ?TOLERANCE|R^@REFDES| @VALUE  ?TOLERANCE|\n.model R^@REFDES RES R=1 DEV=@TOLERANCE%|; COMPGROUP: 1; COMPFIXED: NO; COMPHEIGHT: 0.000; COMPLOC: [3057.633,2026.433]; COMPROT: 0; COMPSIDE: TOP
RA27 = R_Dup2: PSpiceTemplate: R^@REFDES %1 %2 ?TOLERANCE|R^@REFDES| @VALUE  ?TOLERANCE|\n.model R^@REFDES RES R=1 DEV=@TOLERANCE%|; COMPGROUP: 1; COMPFIXED: NO; COMPHEIGHT: 0.000; COMPLOC: [3402.633,1926.433]; COMPROT: 0; COMPSIDE: TOP
RA28 = R_Dup2: PSpiceTemplate: R^@REFDES %1 %2 ?TOLERANCE|R^@REFDES| @VALUE  ?TOLERANCE|\n.model R^@REFDES RES R=1 DEV=@TOLERANCE%|; COMPGROUP: 1; COMPFIXED: NO; COMPHEIGHT: 0.000; COMPLOC: [3457.633,1971.433]; COMPROT: 90; COMPSIDE: TOP
RA29 = R_Dup2: PSpiceTemplate: R^@REFDES %1 %2 ?TOLERANCE|R^@REFDES| @VALUE  ?TOLERANCE|\n.model R^@REFDES RES R=1 DEV=@TOLERANCE%|; COMPGROUP: 1; COMPFIXED: NO; COMPHEIGHT: 0.000; COMPLOC: [3717.633,1936.433]; COMPROT: 90; COMPSIDE: TOP
RA30 = R_Dup2: PSpiceTemplate: R^@REFDES %1 %2 ?TOLERANCE|R^@REFDES| @VALUE  ?TOLERANCE|\n.model R^@REFDES RES R=1 DEV=@TOLERANCE%|; COMPGROUP: 1; COMPFIXED: NO; COMPHEIGHT: 0.000; COMPLOC: [3299.633,1880.000]; COMPROT: 180; COMPSIDE: TOP
RA31 = R_Dup2: PSpiceTemplate: R^@REFDES %1 %2 ?TOLERANCE|R^@REFDES| @VALUE  ?TOLERANCE|\n.model R^@REFDES RES R=1 DEV=@TOLERANCE%|; COMPGROUP: 1; COMPFIXED: NO; COMPHEIGHT: 0.000; COMPLOC: [3344.633,1745.000]; COMPROT: 180; COMPSIDE: TOP
RA32 = R_Dup2: PSpiceTemplate: R^@REFDES %1 %2 ?TOLERANCE|R^@REFDES| @VALUE  ?TOLERANCE|\n.model R^@REFDES RES R=1 DEV=@TOLERANCE%|; COMPGROUP: 1; COMPFIXED: NO; COMPHEIGHT: 0.000; COMPLOC: [3012.633,1536.433]; COMPROT: 90; COMPSIDE: TOP
RA33 = R_Dup2: PSpiceTemplate: R^@REFDES %1 %2 ?TOLERANCE|R^@REFDES| @VALUE  ?TOLERANCE|\n.model R^@REFDES RES R=1 DEV=@TOLERANCE%|; COMPGROUP: 1; COMPFIXED: NO; COMPHEIGHT: 0.000; COMPLOC: [3012.633,1636.433]; COMPROT: 90; COMPSIDE: TOP
RA34 = R_Dup2: PSpiceTemplate: R^@REFDES %1 %2 ?TOLERANCE|R^@REFDES| @VALUE  ?TOLERANCE|\n.model R^@REFDES RES R=1 DEV=@TOLERANCE%|; COMPGROUP: 1; COMPFIXED: NO; COMPHEIGHT: 0.000; COMPLOC: [3402.633,1681.433]; COMPROT: 0; COMPSIDE: TOP
RA35 = R_Dup2: PSpiceTemplate: R^@REFDES %1 %2 ?TOLERANCE|R^@REFDES| @VALUE  ?TOLERANCE|\n.model R^@REFDES RES R=1 DEV=@TOLERANCE%|; COMPGROUP: 1; COMPFIXED: NO; COMPHEIGHT: 0.000; COMPLOC: [3457.633,1636.433]; COMPROT: 270; COMPSIDE: TOP
RA36 = R_Dup2: PSpiceTemplate: R^@REFDES %1 %2 ?TOLERANCE|R^@REFDES| @VALUE  ?TOLERANCE|\n.model R^@REFDES RES R=1 DEV=@TOLERANCE%|; COMPGROUP: 1; COMPFIXED: NO; COMPHEIGHT: 0.000; COMPLOC: [3719.633,1634.000]; COMPROT: 90; COMPSIDE: TOP
RA37 = R_Dup2: PSpiceTemplate: R^@REFDES %1 %2 ?TOLERANCE|R^@REFDES| @VALUE  ?TOLERANCE|\n.model R^@REFDES RES R=1 DEV=@TOLERANCE%|; COMPGROUP: 1; COMPFIXED: NO; COMPHEIGHT: 0.000; COMPLOC: [3112.633,1691.433]; COMPROT: 180; COMPSIDE: TOP
RA38 = R_Dup2: PSpiceTemplate: R^@REFDES %1 %2 ?TOLERANCE|R^@REFDES| @VALUE  ?TOLERANCE|\n.model R^@REFDES RES R=1 DEV=@TOLERANCE%|; COMPGROUP: 1; COMPFIXED: NO; COMPHEIGHT: 0.000; COMPLOC: [3112.633,1636.433]; COMPROT: 180; COMPSIDE: TOP
RA39 = R_Dup2: PSpiceTemplate: R^@REFDES %1 %2 ?TOLERANCE|R^@REFDES| @VALUE  ?TOLERANCE|\n.model R^@REFDES RES R=1 DEV=@TOLERANCE%|; COMPGROUP: 1; COMPFIXED: NO; COMPHEIGHT: 0.000; COMPLOC: [3112.633,1581.433]; COMPROT: 180; COMPSIDE: TOP
RA40 = R_Dup2: PSpiceTemplate: R^@REFDES %1 %2 ?TOLERANCE|R^@REFDES| @VALUE  ?TOLERANCE|\n.model R^@REFDES RES R=1 DEV=@TOLERANCE%|; COMPGROUP: 1; COMPFIXED: NO; COMPHEIGHT: 0.000; COMPLOC: [2737.633,1536.433]; COMPROT: 90; COMPSIDE: TOP
RA41 = R_Dup2: PSpiceTemplate: R^@REFDES %1 %2 ?TOLERANCE|R^@REFDES| @VALUE  ?TOLERANCE|\n.model R^@REFDES RES R=1 DEV=@TOLERANCE%|; COMPGROUP: 1; COMPFIXED: NO; COMPHEIGHT: 0.000; COMPLOC: [2537.633,1586.433]; COMPROT: 90; COMPSIDE: TOP
RA42 = R_Dup2: PSpiceTemplate: R^@REFDES %1 %2 ?TOLERANCE|R^@REFDES| @VALUE  ?TOLERANCE|\n.model R^@REFDES RES R=1 DEV=@TOLERANCE%|; COMPGROUP: 1; COMPFIXED: NO; COMPHEIGHT: 0.000; COMPLOC: [2787.633,1381.433]; COMPROT: 0; COMPSIDE: TOP
RA43 = R_Dup2: PSpiceTemplate: R^@REFDES %1 %2 ?TOLERANCE|R^@REFDES| @VALUE  ?TOLERANCE|\n.model R^@REFDES RES R=1 DEV=@TOLERANCE%|; COMPGROUP: 1; COMPFIXED: NO; COMPHEIGHT: 0.000; COMPLOC: [2232.633,1574.367]; COMPROT: 180; COMPSIDE: TOP
RA44 = R_Dup2: PSpiceTemplate: R^@REFDES %1 %2 ?TOLERANCE|R^@REFDES| @VALUE  ?TOLERANCE|\n.model R^@REFDES RES R=1 DEV=@TOLERANCE%|; COMPGROUP: 1; COMPFIXED: NO; COMPHEIGHT: 0.000; COMPLOC: [2176.633,1629.367]; COMPROT: 180; COMPSIDE: TOP
RA45 = R_Dup2: PSpiceTemplate: R^@REFDES %1 %2 ?TOLERANCE|R^@REFDES| @VALUE  ?TOLERANCE|\n.model R^@REFDES RES R=1 DEV=@TOLERANCE%|; COMPGROUP: 1; COMPFIXED: NO; COMPHEIGHT: 0.000; COMPLOC: [3057.633,1471.433]; COMPROT: 0; COMPSIDE: TOP
RA46 = R_Dup2: PSpiceTemplate: R^@REFDES %1 %2 ?TOLERANCE|R^@REFDES| @VALUE  ?TOLERANCE|\n.model R^@REFDES RES R=1 DEV=@TOLERANCE%|; COMPGROUP: 1; COMPFIXED: NO; COMPHEIGHT: 0.000; COMPLOC: [2887.633,1381.433]; COMPROT: 0; COMPSIDE: TOP
RA47 = R_Dup2: PSpiceTemplate: R^@REFDES %1 %2 ?TOLERANCE|R^@REFDES| @VALUE  ?TOLERANCE|\n.model R^@REFDES RES R=1 DEV=@TOLERANCE%|; COMPGROUP: 1; COMPFIXED: NO; COMPHEIGHT: 0.000; COMPLOC: [3012.633,1471.433]; COMPROT: 270; COMPSIDE: TOP
RA48 = R_Dup2: PSpiceTemplate: R^@REFDES %1 %2 ?TOLERANCE|R^@REFDES| @VALUE  ?TOLERANCE|\n.model R^@REFDES RES R=1 DEV=@TOLERANCE%|; COMPGROUP: 1; COMPFIXED: NO; COMPHEIGHT: 0.000; COMPLOC: [3057.633,1526.433]; COMPROT: 0; COMPSIDE: TOP
RA49 = R_Dup2: PSpiceTemplate: R^@REFDES %1 %2 ?TOLERANCE|R^@REFDES| @VALUE  ?TOLERANCE|\n.model R^@REFDES RES R=1 DEV=@TOLERANCE%|; COMPGROUP: 1; COMPFIXED: NO; COMPHEIGHT: 0.000; COMPLOC: [2276.633,1628.367]; COMPROT: 180; COMPSIDE: TOP
RA50 = R_Dup2: PSpiceTemplate: R^@REFDES %1 %2 ?TOLERANCE|R^@REFDES| @VALUE  ?TOLERANCE|\n.model R^@REFDES RES R=1 DEV=@TOLERANCE%|; COMPGROUP: 1; COMPFIXED: NO; COMPHEIGHT: 0.000; COMPLOC: [3057.633,1416.433]; COMPROT: 0; COMPSIDE: TOP
RA51 = R_Dup2: PSpiceTemplate: R^@REFDES %1 %2 ?TOLERANCE|R^@REFDES| @VALUE  ?TOLERANCE|\n.model R^@REFDES RES R=1 DEV=@TOLERANCE%|; COMPGROUP: 1; COMPFIXED: NO; COMPHEIGHT: 0.000; COMPLOC: [3402.633,1426.433]; COMPROT: 0; COMPSIDE: TOP
RA52 = R_Dup2: PSpiceTemplate: R^@REFDES %1 %2 ?TOLERANCE|R^@REFDES| @VALUE  ?TOLERANCE|\n.model R^@REFDES RES R=1 DEV=@TOLERANCE%|; COMPGROUP: 1; COMPFIXED: NO; COMPHEIGHT: 0.000; COMPLOC: [3457.633,1471.433]; COMPROT: 90; COMPSIDE: TOP
RA53 = R_Dup2: PSpiceTemplate: R^@REFDES %1 %2 ?TOLERANCE|R^@REFDES| @VALUE  ?TOLERANCE|\n.model R^@REFDES RES R=1 DEV=@TOLERANCE%|; COMPGROUP: 1; COMPFIXED: NO; COMPHEIGHT: 0.000; COMPLOC: [3720.633,1433.433]; COMPROT: 90; COMPSIDE: TOP
RA54 = R_Dup2: PSpiceTemplate: R^@REFDES %1 %2 ?TOLERANCE|R^@REFDES| @VALUE  ?TOLERANCE|\n.model R^@REFDES RES R=1 DEV=@TOLERANCE%|; COMPGROUP: 1; COMPFIXED: NO; COMPHEIGHT: 0.000; COMPLOC: [1961.633,1632.367]; COMPROT: 270; COMPSIDE: TOP
RA55 = R_Dup2: PSpiceTemplate: R^@REFDES %1 %2 ?TOLERANCE|R^@REFDES| @VALUE  ?TOLERANCE|\n.model R^@REFDES RES R=1 DEV=@TOLERANCE%|; COMPGROUP: 1; COMPFIXED: NO; COMPHEIGHT: 0.000; COMPLOC: [3304.633,1380.000]; COMPROT: 180; COMPSIDE: TOP
RA56 = R_Dup2: PSpiceTemplate: R^@REFDES %1 %2 ?TOLERANCE|R^@REFDES| @VALUE  ?TOLERANCE|\n.model R^@REFDES RES R=1 DEV=@TOLERANCE%|; COMPGROUP: 1; COMPFIXED: NO; COMPHEIGHT: 0.000; COMPLOC: [2067.633,1624.367]; COMPROT: 90; COMPSIDE: TOP
UA1 = LTC2299 ADC x2_3: COMPGROUP: 1; COMPFIXED: NO; COMPHEIGHT: 0.000; COMPLOC: [2148.200,1762.000]; COMPROT: 90; COMPSIDE: TOP
UA2 = THS4131_DiffAmp_0: COMPGROUP: 1; COMPFIXED: NO; COMPHEIGHT: 0.000; COMPLOC: [2942.633,2146.433]; COMPROT: 180; COMPSIDE: TOP
UA3 = SN74CBT3253C 4MUX: COMPGROUP: 1; COMPFIXED: NO; COMPHEIGHT: 0.000; COMPLOC: [3182.633,1941.433]; COMPROT: 0; COMPSIDE: TOP
UA4 = THS4131_DiffAmp_0: COMPGROUP: 1; COMPFIXED: NO; COMPHEIGHT: 0.000; COMPLOC: [3667.633,2161.433]; COMPROT: 180; COMPSIDE: TOP
UA5 = THS4131_DiffAmp_0: COMPGROUP: 1; COMPFIXED: NO; COMPHEIGHT: 0.000; COMPLOC: [2942.633,1651.433]; COMPROT: 180; COMPSIDE: TOP
UA6 = SN74CBT3253C 4MUX: COMPGROUP: 1; COMPFIXED: NO; COMPHEIGHT: 0.000; COMPLOC: [3182.633,1441.433]; COMPROT: 0; COMPSIDE: TOP
UA7 = THS4131_DiffAmp_0: COMPGROUP: 1; COMPFIXED: NO; COMPHEIGHT: 0.000; COMPLOC: [3667.633,1661.433]; COMPROT: 180; COMPSIDE: TOP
